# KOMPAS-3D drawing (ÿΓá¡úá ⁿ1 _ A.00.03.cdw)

Views: Спереди 1, Спереди, Проекционный вид 2, Изометрия XYZ 3, Изометрия XYZ, Разрез А-А
Referenced files in C:\Users\s.slezkin\Desktop\Раскатчик арок 2\: Штанга №1 _ A.00.03.m3d, Штанга №1 _ A.00.03.cdw
Referenced files in C:\Program Files (x86)\ASCON\KOMPAS-3D V15\Libs\PartLib\DATA\vault\Methods\Kompas\3D\: PLib_Nut_OST92_900.m3d
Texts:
  Штанга №1
  http://vk.com/sergey_krd
  Гайка М10х1,5-6Н
  ГОСТ 2524-70
  Труба 15х2
  ГОСТ 8734-75
  1. Трубу 15х2 (ГОСТ 8734-75) и гайку М10х1,5-6Н
  приварить по ГОСТ 5264-80;
  2. Штангу изготовить из трубы стальной квадратной
  Гайка М10-6H ГОСТ 2524-70
Dimensions and other numbers on the sheet: 155; 35; 25; 10; 18; 15; 55; 50; 60,84; 20; 14; 4; 11; 50х50х4 ГОСТ 8639-82.; 1:1; 1; 0,83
